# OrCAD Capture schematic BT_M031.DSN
size B; title: BT_N031; rev: 1.0; note: MTK1389DQ
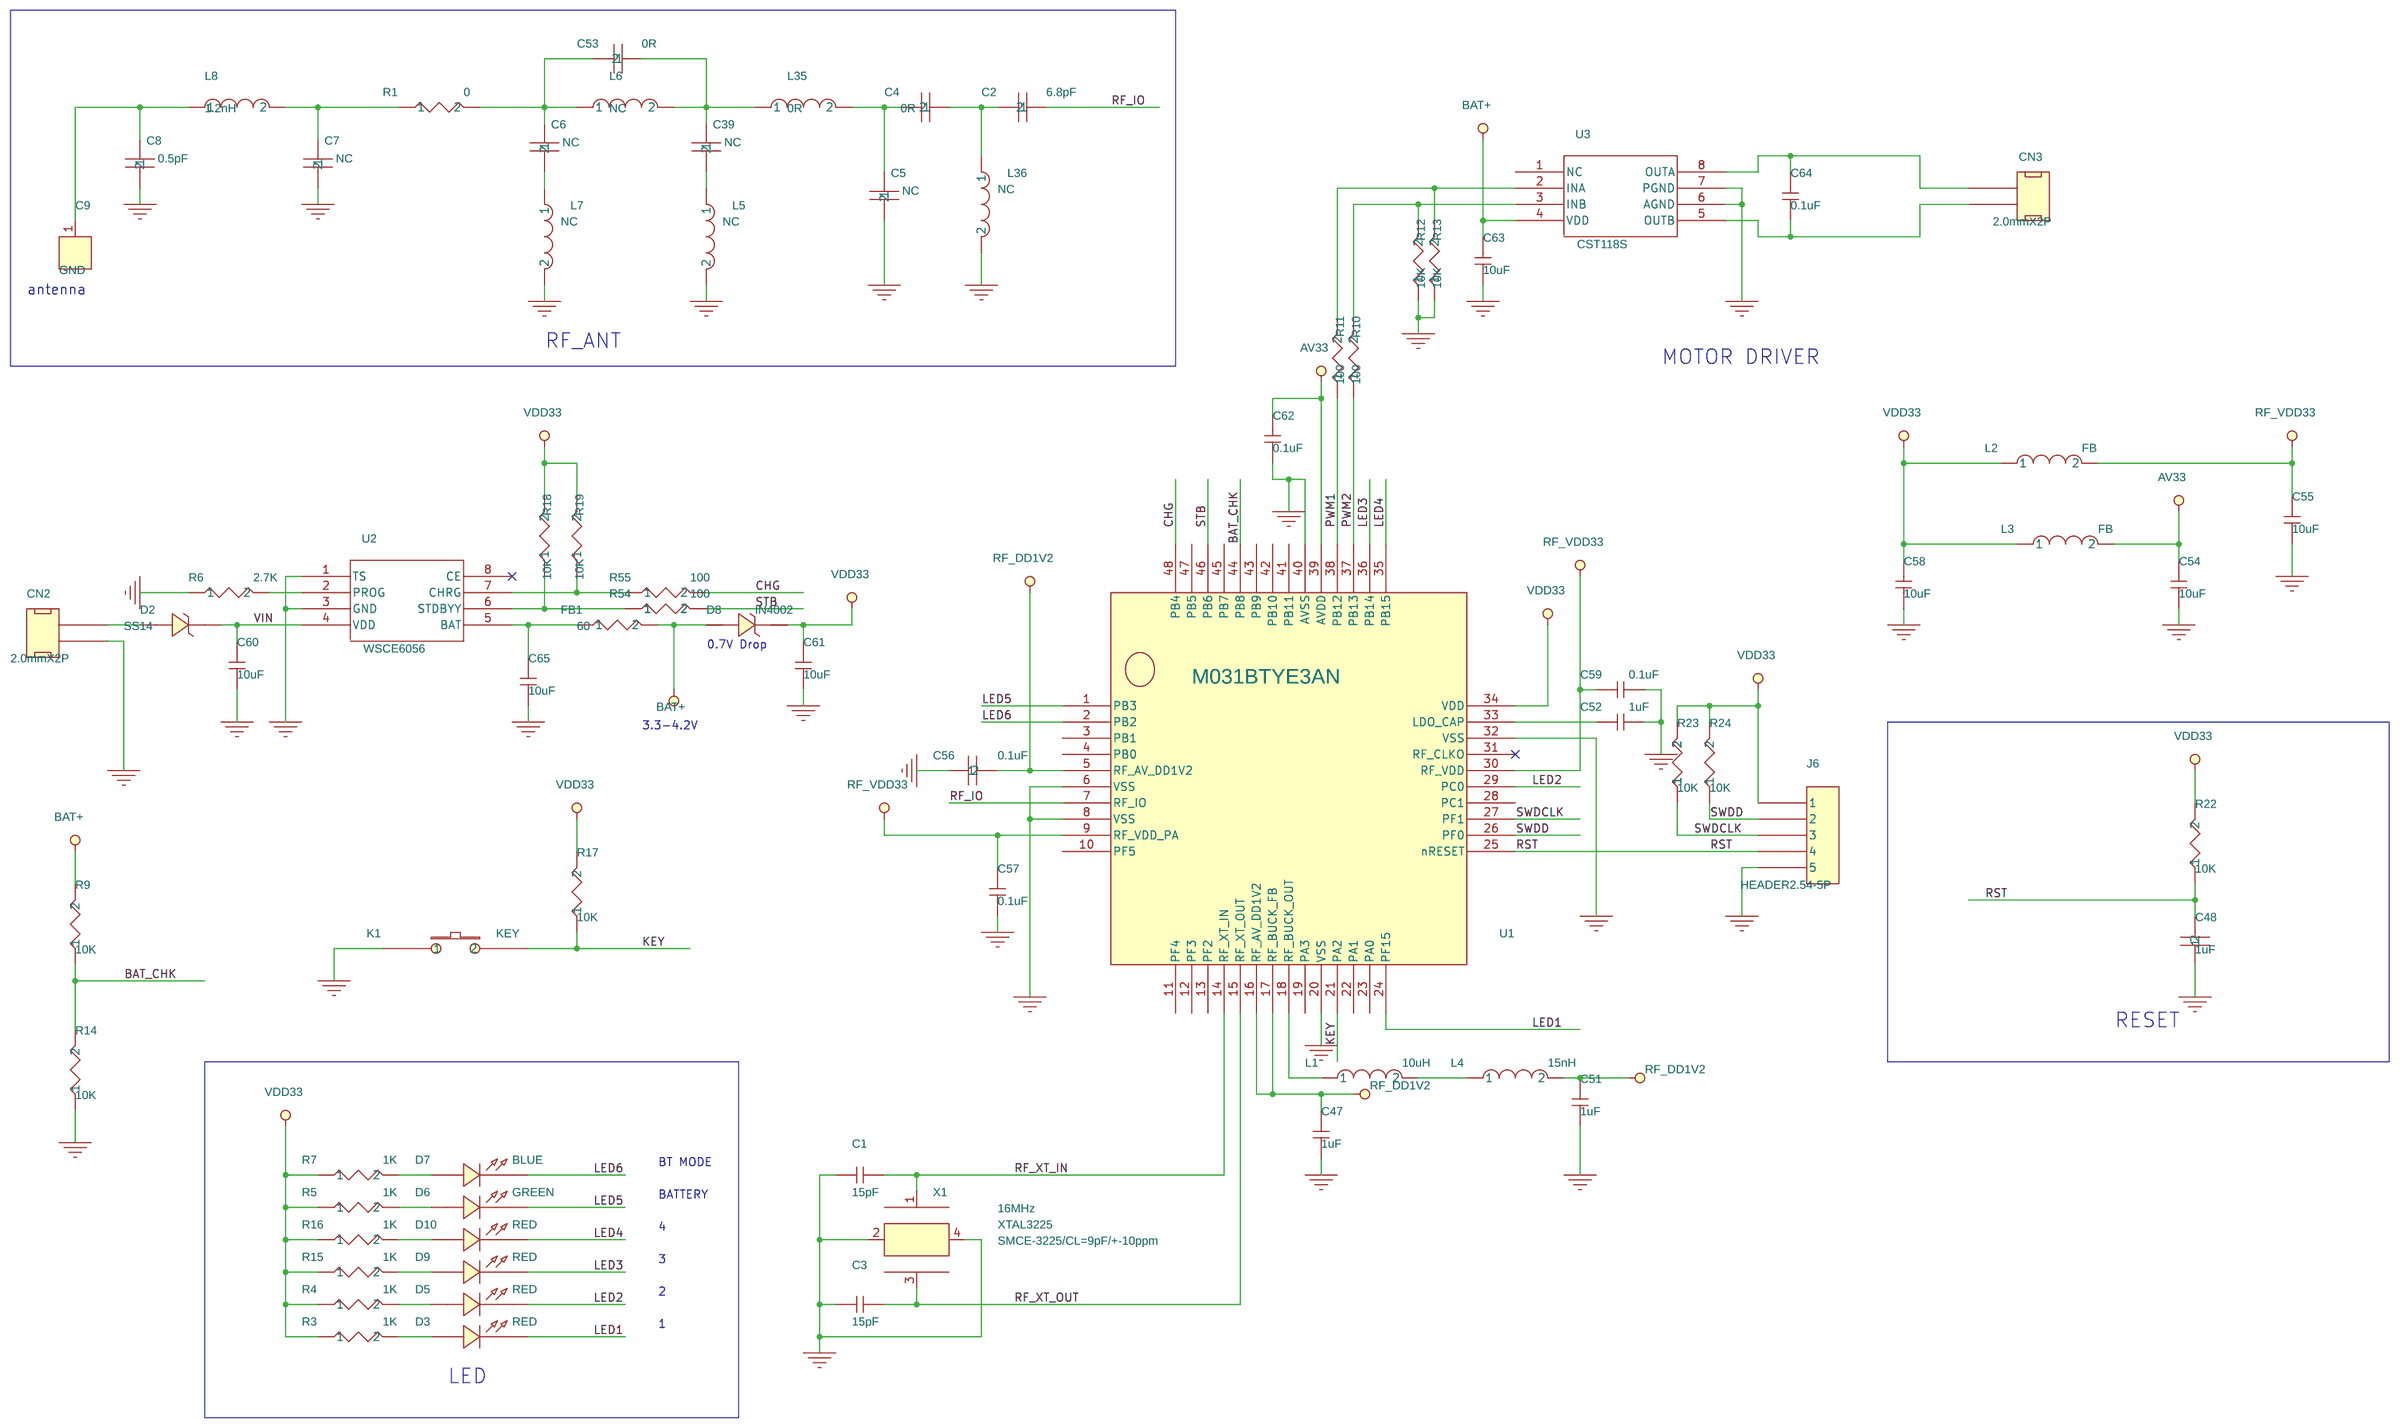
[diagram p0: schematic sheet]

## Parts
C1  15pF  [C0402]
C2  6.8pF  [C0402]
C3  15pF  [C0402]
C4  0R  [C0402]
C5  NC  [C0402]
C6  NC  [C0402]
C7  NC  [C0402]
C8  0.5pF  [C0402]
C9  GND  [antenna_p]
C39  NC  [C0402]
C47  1uF  [C0402]
C48  1uF  [C0603]
C51  1uF  [C0402]
C52  1uF  [C0402]
C53  0R  [C0402]
C54  10uF  [C0402]
C55  10uF  [C0402]
C56  0.1uF  [C0603]
C57  0.1uF  [C0402]
C58  10uF  [C0402]
C59  0.1uF  [C0402]
C60  10uF  [C0402]
C61  10uF  [C0402]
C62  0.1uF  [C0402]
C63  10uF  [C0402]
C64  0.1uF  [C0402]
C65  10uF  [C0402]
CN2  2.0mmX2P  [CON2-2.0B]
CN3  2.0mmX2P  [CON2-2.0B]
D2  SS14  [STD-202E]
D3  RED  [LED_0]
D5  RED  [LED_0]
D6  GREEN  [LED_0]
D7  BLUE  [LED_0]
D8  IN4002  [STD-202E]
D9  RED  [LED_0]
D10  RED  [LED_0]
FB1  60  [R0402]
J6  HEADER2.54-5P  [CN-5P2]
K1  KEY  [KEY2]
L1  10uH  [R0603]
L2  FB  [R0603]
L3  FB  [R0603]
L4  15nH  [R0603]
L5  NC  [R0402]
L6  NC  [R0402]
L7  NC  [R0402]
L8  1.2nH  [C0402]
L35  0R  [R0402]
L36  NC  [R0402]
R1  0  [R0603]
R3  1K  [R0603]
R4  1K  [R0603]
R5  1K  [R0603]
R6  2.7K  [R0603]
R7  1K  [R0603]
R9  10K  [R0603]
R10  100  [R0603]
R11  100  [R0603]
R12  10K  [R0603]
R13  10K  [R0603]
R14  10K  [R0603]
R15  1K  [R0603]
R16  1K  [R0603]
R17  10K  [R0603]
R18  10K  [R0603]
R19  10K  [R0603]
R22  10K  [R0603]
R23  10K  [R0603]
R24  10K  [R0603]
R54  100  [R0603]
R55  100  [R0603]
U1  M031BTYE3AN  [MCU_QFN48_5X5MM]
U2  WSCE6056  [SOP8]
U3  CST118S  [SOP8]
X1  16MHz  [XTAL3225]

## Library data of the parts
C1 C3 C47 C51 C52 C54 C55 C57-C65 = CAPACITOR
C2 = CAP-C_1: Package: 0603
C4 = CAP-C: Package: 0603
C5 = CAP-C_2: Package: 0603
C6 = CAP-C_3: Package: 0603
C7 = CAP-C_7: Package: 0603
C8 = CAP-C_6: Package: 0603
C9 = JUMPER3X1_0
C39 = CAP-C_5: Package: 0603
C48 = C0603
C53 = CAP-C_4: Package: 0603
C56 = C_20p
CN2 CN3 = CONN_2_DIP_2.0
D2 D8 = DIODE_ZENER
D3 D5-D7 D9 D10 = LED: AppProp: mN=LED,fV=3,fC=20E-3; BV: 5; IBV: 10e-6; IF: 30E-3; IS: 1.7603e-27; PDM: 100E-3; RS: 2; VR: 5
FB1 = R_0_10
J6 = CON4_3
K1 = SW_PUSHBUTTON
L1 = INDUCTOR_3: Part Number: Murata/ LQG15HS1N8B02
L2 = INDUCTOR_5: Package: L0603; Part Number: Murata/ LQG15HS1N8B02
L3 = INDUCTOR_2: Package: L0603; Part Number: Murata/ LQG15HS1N8B02
L4 = INDUCTOR_1: Part Number: Murata/ LQG15HS1N8B02
L5 = INDUCTOR: Package: L0603; Part Number: Sunlord/ SDCL1005C1NOSTDF
L6 = INDUCTOR_6: Package: L0603; Part Number: Murata/ LQG15HS1N8B02
L7 = INDUCTOR_9: Package: L0603; Part Number: Sunlord/ SDCL1005C1NOSTDF
L8 = INDUCTOR_7: Package: L0603; Part Number: Sunlord/ SDCL1005C1N2STDF
L35 = INDUCTOR_4: Package: L0603; Part Number: Murata/ LQG15HS1N8B02
L36 = INDUCTOR_8: Package: L0603; Part Number: Sunlord/ SDCL1005C1NOSTDF
R1 = R0603_2
R3 = R0603_7
R4 = R0603_1
R5 = R0603_5
R6 = R_0_5
R7 = R0603_11
R9 = R_0_6
R10 = R_0
R11 = R_0_2
R12 = R_0_9
R13 = R_0_8
R14 = R_0_1
R15 = R0603_10
R16 = R0603_4
R17 = R_0_4
R18 = R_0_7
R19 = R_0_3
R22 = R0603_6
R23 = R0603_9
R24 = R0603_8
R54 = R0603_3
R55 = R0603
U1 = N031BT_3
U2 = CST118S_0
U3 = CST118S
X1 = X_0: Part Number: SMCE-3225/CL=9pF/+-10ppm

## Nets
AV33: C54.2 C62.2 L3.2 U1.39(AVDD)
GND: C1.1 C3.1 C5.2 C7.2 C8.2 C47.1 C48.1 C51.1 C52.1 C54.1 C55.1 C56.1 C57.1 C58.1 C59.1 C60.1 C61.1 C62.1 C63.1 C65.1 CN2.1 J6.5 K1.1 L5.2 L7.2 L36.2 R6.1 R12.1 R13.1 R14.1 U1.6(VSS) U1.8(VSS) U1.20(VSS) U1.32(VSS) U1.40(AVSS) U2.1(TS) U2.3(GND) U3.6(AGND) U3.7(PGND) X1.2 X1.4
VDD33: C58.2 C61.2 D8.2(CATHODE) J6.1 L2.1 L3.1 R3.1 R4.1 R5.1 R7.1 R15.1 R16.1 R17.2 R18.2 R19.2 R22.2 R23.2 R24.2 U1.34(VDD)
VIN: C60.2 D2.2(CATHODE) U2.4(VDD)
BAT+: C63.2 D8.1(ANODE) FB1.2 R9.2 U3.4(VDD)
BAT_CHK: R9.1 R14.2 U1.44(PB8)
CHG: R55.2 U1.48(PB4)
KEY: K1.2 R17.1 U1.21(PA2)
LED1: D3.2 U1.24(PF15)
LED2: D5.2 U1.29(PC0)
LED3: D9.2 U1.36(PB14)
LED4: D10.2 U1.35(PB15)
LED5: D6.2 U1.1(PB3)
LED6: D7.2 U1.2(PB2)
PWM1: R11.1 U1.38(PB12)
PWM2: R10.1 U1.37(PB13)
RF_DD1V2: C47.2 C51.2 C56.2 L4.2 U1.5(RF_AV_DD1V2) U1.16(RF_AV_DD1V2) U1.17(RF_BUCK_FB)
RF_IO: C2.1 U1.7(RF_IO)
RF_VDD33: C55.2 C57.2 C59.2 L2.2 U1.9(RF_VDD_PA) U1.30(RF_VDD)
RF_XT_IN: C1.2 U1.14(RF_XT_IN) X1.1
RF_XT_OUT: C3.2 U1.15(RF_XT_OUT) X1.3
RST: C48.2 J6.4 R22.1 U1.25(nRESET)
STB: R54.2 U1.46(PB6)
SWDCLK: J6.3 R23.1 U1.27(PF1)
SWDD: J6.2 R24.1 U1.26(PF0)
N25113237: D3.1 R3.2
N25191966: C8.1 C9.1 L8.1
N25191994: C6.1 C53.2 L6.1 R1.2
N25192081: C7.1 L8.2 R1.1
N25192164: C2.2 C4.1 L36.1
N25198709: L1.1 U1.18(RF_BUCK_OUT)
N25200643: C52.2 U1.33(LDO_CAP)
N25205742: C65.2 FB1.1 U2.5(BAT)
N25208907: C64.2 CN3.2 U3.8(OUTA)
N25208919: C64.1 CN3.1 U3.5(OUTB)
N25213309: CN2.2 D2.1(ANODE)
N25213966: R6.2 U2.2(PROG)
N25215294: R10.2 R12.2 U3.3(INB)
N25215299: R11.2 R13.2 U3.2(INA)
N25216701: D10.1 R16.2
N25216704: D9.1 R15.2
N25216707: D5.1 R4.2
N25217939: R19.1 R55.1 U2.7(CHRG)
N25217942: R18.1 R54.1 U2.6(STDBYY)
N25218647: D6.1 R5.2
N25218650: D7.1 R7.2
N25221698: L1.2 L4.1
N25223539: C4.2 C5.1 L35.2
N25224273: C39.1 C53.1 L6.2 L35.1
N25224283: C39.2 L5.1
N25226056: C6.2 L7.1

Not connected (* = marked no-connect by the designer): U1 3(PB1) 4(PB0) 10(PF5) 11(PF4) 12(PF3) 13(PF2) 19(PA3) 22(PA1) 23(PA0) 28(PC1) 31(RF_CLKO)* 41(PB11) 42(PB10) 43(PB9) 45(PB7) 47(PB5); U2 8(CE)*; U3 1(NC)

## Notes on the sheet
- antenna
- RF_ANT
- MOTOR DRIVER
- 0.7V Drop
- 3.3-4.2V
- RESET
- BT MODE
- BATTERY
- 4
- 3
- 2
- 1
- LED
